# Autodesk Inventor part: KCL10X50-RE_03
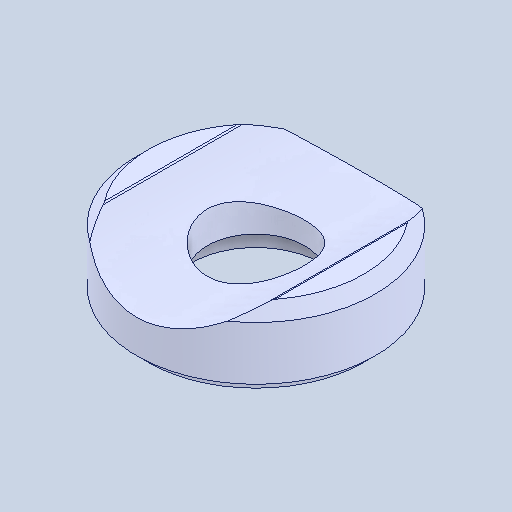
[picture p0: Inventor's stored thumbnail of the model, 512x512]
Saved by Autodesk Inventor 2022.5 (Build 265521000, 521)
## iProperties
Created: 2024-08
Part Number: KCL10X50-RE_03
Material: 一般
Document SubType Name: Modeling
Designer: ImaoCorp
Density: 1 g/cm^3
Appearance: 既定
Author: ImaoCorp
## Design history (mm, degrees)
feature "KCL10X50-RE_03"
node "ソリッド1"
